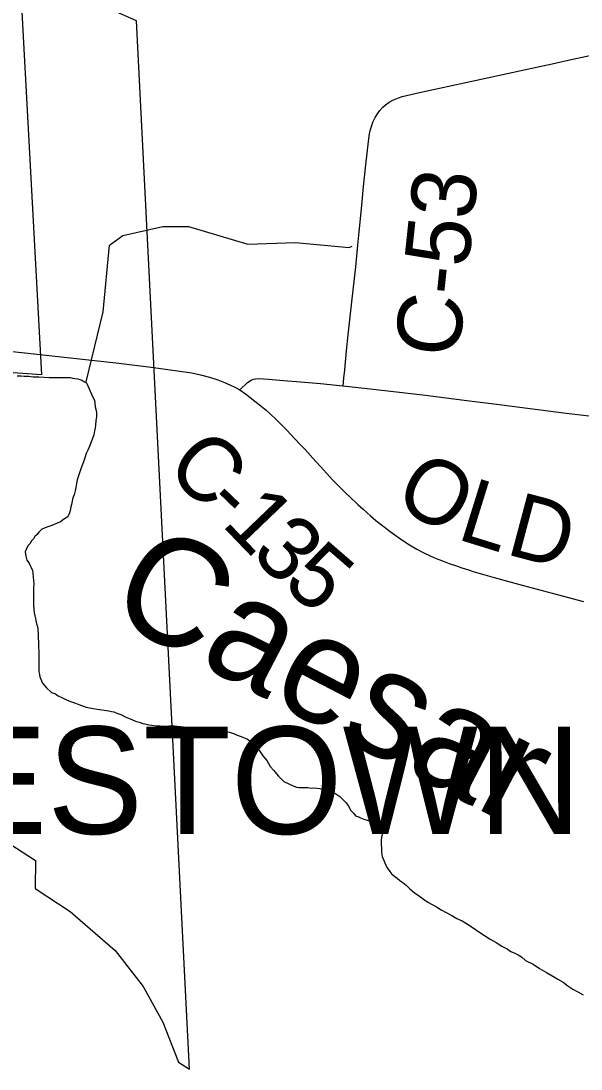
# Model space of a CAD drawing. Extents: x -5.4 to 49.9, y 13.2 to 48.4.
# Drawn here: x 30.099 to 30.593, y 42.966 to 43.891 of the extents above; entities that cross this region are included whole.
import ezdxf

# ---------------------------------------------------------------- set-up
doc = ezdxf.new("R2010")
doc.units = 0
for name, color, linetype in [('GM_X_Corporation', 7, 'Continuous'), ('GM_X_Corporation_Text', 7, 'Continuous'), ('GM_X_County_Road', 7, 'Continuous'), ('GM_X_County_Road_Text', 7, 'Continuous'), ('GM_X_Minor_River', 7, 'Continuous'), ('GM_X_Minor_River_Text', 7, 'Continuous'), ('GM_X_State_Route', 7, 'Continuous')]:
    doc.layers.add(name, color=color, linetype=linetype)

msp = doc.modelspace()

# ---------------------------------------------------------------- linework, layer by layer
at = {"layer": 'GM_X_Corporation'}
for points in [[(30.0978, 43.93683), (30.11717, 43.57845), (30.00085, 43.58666), (30.01955, 43.85142), (30.01808, 43.85261), (30.01694, 43.88966), (29.99211, 43.89093)], [(29.28308, 43.68973), (29.34531, 43.6481), (30.11202, 43.14996), (30.11178, 43.12523), (30.14245, 43.10478), (30.18213, 43.0705), (30.20678, 43.03863), (30.22422, 43.00735), (30.23805, 42.97187), (30.24767, 42.96585), (30.20088, 43.89052), (30.17852, 43.90074)]]:
    msp.add_lwpolyline(points, dxfattribs=at)
at = {"layer": 'GM_X_County_Road'}
for points in [[(30.38315, 43.56867), (30.38383, 43.5753), (30.38459, 43.5827), (30.38617, 43.5994), (30.38769, 43.61361), (30.39088, 43.64264), (30.39438, 43.67348), (30.3961, 43.69266), (30.39726, 43.70441), (30.39932, 43.72481), (30.40126, 43.74459), (30.40332, 43.76371), (30.40549, 43.78411), (30.40656, 43.79093), (30.40731, 43.79472), (30.40846, 43.79846), (30.40944, 43.80126), (30.41136, 43.80527), (30.41334, 43.80854), (30.41562, 43.81161), (30.41821, 43.81441), (30.42055, 43.81655), (30.42365, 43.81883), (30.42643, 43.8204), (30.42912, 43.82164), (30.43186, 43.82271), (30.43522, 43.82378), (30.45042, 43.82733), (30.46803, 43.83121), (30.48989, 43.83595), (30.5494, 43.8488), (30.56758, 43.85286), (30.58154, 43.85594), (30.65259, 43.87134)], [(30.29211, 43.56501), (30.29708, 43.56164), (30.30097, 43.55862), (30.30428, 43.556), (30.30774, 43.5534), (30.31105, 43.55068), (30.31531, 43.54711), (30.31896, 43.54379), (30.32434, 43.53868), (30.32872, 43.53432), (30.33353, 43.52949), (30.33692, 43.52589), (30.34496, 43.51728), (30.34966, 43.51232), (30.3589, 43.50229), (30.36351, 43.49726), (30.37396, 43.48577), (30.3791, 43.48035), (30.38521, 43.47413), (30.38927, 43.47027), (30.39608, 43.46388), (30.40071, 43.45971), (30.40724, 43.45395), (30.41202, 43.44996), (30.4193, 43.4441), (30.42478, 43.43998), (30.43085, 43.43561), (30.43499, 43.43282), (30.44181, 43.42844), (30.44824, 43.42461), (30.45426, 43.42131), (30.45991, 43.41862), (30.46507, 43.41639), (30.47086, 43.4141), (30.4767, 43.41193), (30.48316, 43.40968), (30.48788, 43.40809), (30.49381, 43.40621), (30.49796, 43.40491), (30.50271, 43.40345), (30.50806, 43.4018), (30.51642, 43.39941), (30.53138, 43.3954), (30.54096, 43.39279), (30.56734, 43.38565), (30.59496, 43.37833)]]:
    msp.add_lwpolyline(points, dxfattribs=at)
at = {"layer": 'GM_X_Minor_River'}
for points in [[(30.15659, 43.57208), (30.1716, 43.63393), (30.17719, 43.69269), (30.18909, 43.70121), (30.2241, 43.70931), (30.24683, 43.70927), (30.29923, 43.69351), (30.34132, 43.69502), (30.38861, 43.69074), (30.39128, 43.69183)], [(30.09592, 43.57756), (30.09933, 43.57752), (30.10199, 43.57712), (30.10578, 43.57707), (30.10995, 43.57665), (30.11488, 43.57659), (30.11943, 43.57616), (30.12398, 43.57611), (30.12853, 43.57606), (30.13233, 43.57601), (30.13612, 43.57597), (30.13953, 43.57593), (30.14257, 43.5759), (30.14446, 43.5755), (30.14635, 43.5751), (30.14939, 43.57468), (30.15279, 43.5735), (30.15467, 43.57234), (30.15694, 43.57118), (30.1625, 43.55858), (30.16399, 43.5559), (30.16434, 43.55323), (30.16468, 43.55019), (30.1654, 43.54676), (30.16576, 43.54486), (30.16573, 43.54144), (30.16531, 43.53765), (30.16489, 43.53385), (30.16449, 43.53158), (30.16408, 43.52892), (30.16328, 43.52551), (30.16211, 43.5221), (30.16094, 43.51908), (30.15977, 43.51605), (30.15821, 43.51189), (30.15666, 43.50887), (30.15548, 43.50508), (30.1543, 43.50167), (30.15274, 43.49789), (30.15157, 43.49448), (30.15078, 43.49183), (30.14961, 43.48843), (30.14882, 43.48578), (30.14803, 43.48237), (30.14761, 43.47895), (30.14682, 43.47592), (30.14603, 43.47251), (30.14486, 43.46986), (30.14445, 43.46683), (30.14366, 43.4638), (30.14326, 43.4619), (30.14246, 43.45849), (30.14206, 43.4566), (30.14051, 43.45319), (30.13669, 43.45058), (30.13401, 43.44871), (30.13058, 43.44723), (30.12639, 43.44537), (30.12296, 43.44427), (30.11763, 43.44205), (30.11494, 43.43942), (30.1134, 43.43754), (30.11149, 43.43566), (30.11033, 43.43378), (30.10841, 43.4319), (30.10687, 43.42926), (30.10533, 43.42737), (30.10378, 43.42435), (30.103, 43.42208), (30.10334, 43.41828), (30.10444, 43.41484), (30.10631, 43.41216), (30.10742, 43.41025), (30.10816, 43.40834), (30.10927, 43.40567), (30.10963, 43.40339), (30.10997, 43.39996), (30.11032, 43.39692)], [(30.11032, 43.39692), (30.11066, 43.39388), (30.11025, 43.39046), (30.11021, 43.38704), (30.11018, 43.38438), (30.11015, 43.38096), (30.11012, 43.3783), (30.11008, 43.37489), (30.11043, 43.37146), (30.11077, 43.36842), (30.1115, 43.36575), (30.11186, 43.36347), (30.11222, 43.36156), (30.11295, 43.35851), (30.11368, 43.35623), (30.11403, 43.35356), (30.11437, 43.34976), (30.11434, 43.34672), (30.11467, 43.34216), (30.11462, 43.33798), (30.11497, 43.33456), (30.11488, 43.32582), (30.11485, 43.32316), (30.11482, 43.32088), (30.1148, 43.3186), (30.11478, 43.31632), (30.11551, 43.31403), (30.11586, 43.31175), (30.11808, 43.3064), (30.12183, 43.30218), (30.12596, 43.29796), (30.12974, 43.29677), (30.132, 43.29523), (30.13578, 43.29329), (30.13993, 43.29134), (30.14371, 43.28978), (30.14711, 43.2886), (30.15013, 43.28743), (30.1524, 43.28664), (30.15429, 43.28586), (30.15656, 43.28507), (30.15959, 43.28466), (30.163, 43.28386), (30.16641, 43.28344), (30.17663, 43.28181), (30.17891, 43.2814), (30.18118, 43.281), (30.18382, 43.27983), (30.18723, 43.27865), (30.191, 43.27671), (30.19553, 43.27476), (30.20006, 43.27281), (30.20422, 43.27162), (30.20649, 43.27083), (30.20838, 43.27043), (30.21179, 43.26963), (30.21444, 43.26922), (30.21823, 43.2688), (30.22203, 43.26876), (30.22582, 43.26834), (30.22962, 43.26867), (30.23417, 43.26862), (30.23985, 43.26818), (30.24516, 43.26736), (30.25046, 43.26654), (30.25691, 43.26609), (30.26183, 43.26565), (30.26524, 43.26523), (30.2679, 43.2652), (30.27018, 43.26518), (30.27359, 43.26476), (30.27586, 43.26473), (30.27776, 43.26433), (30.2804, 43.26354), (30.28306, 43.26313), (30.28646, 43.26195), (30.28986, 43.2604), (30.29326, 43.25922), (30.29893, 43.25687), (30.30156, 43.25494), (30.30419, 43.25264), (30.30682, 43.24995), (30.30944, 43.2465), (30.31243, 43.24228), (30.3158, 43.23807), (30.31878, 43.23271), (30.32216, 43.22926), (30.3244, 43.22619), (30.32628, 43.22427), (30.32853, 43.22197), (30.33078, 43.21966), (30.33984, 43.21538), (30.34211, 43.21459), (30.344, 43.21419), (30.3478, 43.21415), (30.3497, 43.21413), (30.35197, 43.2141), (30.35462, 43.21369), (30.3569, 43.21405), (30.35993, 43.21363), (30.36258, 43.21323)], [(30.36258, 43.21323), (30.36561, 43.21243), (30.36902, 43.21163), (30.37205, 43.21084), (30.37393, 43.21006), (30.37582, 43.20928), (30.37846, 43.20735), (30.38034, 43.20619), (30.38222, 43.20426), (30.3841, 43.20234), (30.38598, 43.2008), (30.38784, 43.19774), (30.39008, 43.19392), (30.39271, 43.19123), (30.39421, 43.18931), (30.39609, 43.18853), (30.39836, 43.18737), (30.40138, 43.18619), (30.40441, 43.1854), (30.40706, 43.18461), (30.40933, 43.1842), (30.41196, 43.18265), (30.41346, 43.18074), (30.41534, 43.17881), (30.41645, 43.17614), (30.41756, 43.17309), (30.41715, 43.17044), (30.41674, 43.16778), (30.41671, 43.16436), (30.41704, 43.16056), (30.417, 43.15676), (30.41773, 43.15333), (30.4218, 43.14379), (30.42367, 43.14111), (30.42591, 43.13804), (30.42855, 43.13611), (30.4308, 43.13419), (30.43306, 43.13226), (30.4357, 43.13033), (30.43871, 43.12802), (30.44209, 43.12494), (30.44585, 43.12148), (30.45037, 43.11839), (30.45413, 43.11569), (30.4579, 43.11298), (30.46167, 43.11104), (30.46544, 43.1091), (30.46959, 43.10639), (30.47412, 43.10406), (30.47902, 43.10135), (30.48355, 43.09864), (30.48808, 43.09669), (30.49185, 43.09436), (30.49788, 43.0905), (30.50278, 43.08702), (30.50767, 43.08355), (30.51295, 43.08045), (30.51823, 43.07735), (30.52313, 43.07426), (30.52766, 43.07192), (30.53105, 43.06961), (30.53444, 43.06805), (30.53746, 43.0665), (30.54048, 43.06494), (30.54386, 43.06148), (30.55066, 43.05837), (30.55631, 43.0545), (30.56234, 43.05102), (30.568, 43.04791), (30.57252, 43.0452), (30.57705, 43.04249), (30.58119, 43.0394), (30.58571, 43.03631), (30.59024, 43.03398), (30.59476, 43.03127)]]:
    msp.add_lwpolyline(points, dxfattribs=at)
at = {"layer": 'GM_X_State_Route'}
for points in [[(30.0288, 43.60393), (30.0298, 43.60387), (30.0307, 43.60382), (30.06198, 43.60198), (30.0891, 43.59908), (30.15088, 43.59232), (30.18547, 43.58851), (30.21386, 43.58513), (30.23726, 43.58194), (30.24978, 43.58024), (30.25757, 43.57846), (30.26537, 43.57634), (30.27263, 43.57386), (30.27847, 43.57156), (30.28343, 43.56943), (30.28822, 43.56713), (30.29211, 43.56501)], [(30.29211, 43.56501), (30.29894, 43.57161), (30.30225, 43.57357), (30.30407, 43.57439), (30.30601, 43.57489), (30.30865, 43.57505), (30.31743, 43.57455), (30.33412, 43.57311), (30.34215, 43.5724), (30.36318, 43.57063), (30.38296, 43.56869), (30.38315, 43.56867), (30.40703, 43.56601), (30.45334, 43.56071), (30.49218, 43.55576), (30.52299, 43.55176), (30.57971, 43.54464), (30.60006, 43.54221)]]:
    msp.add_lwpolyline(points, dxfattribs=at)

# ---------------------------------------------------------------- texts
at = {"layer": 'GM_X_Corporation_Text'}
msp.add_text('JAMESTOWN', height=0.094697, rotation=0.00001, dxfattribs=at).set_placement((29.78462, 43.1733))
at = {"layer": 'GM_X_County_Road_Text'}
for s, height, rotation, p in [('C-53', 0.056818, 83.92038, (30.48495, 43.59254)), ('C', 0.05682, 316.66716, (30.22491, 43.49407)), ('O', 0.05682, 328.99939, (30.4258, 43.46563)), ('L', 0.05682, 342.74121, (30.48221, 43.43381)), ('-', 0.05682, 316.06531, (30.25874, 43.46216)), ('1', 0.05682, 313.82246, (30.27513, 43.44638)), ('D', 0.05682, 345.15027, (30.5253, 43.42048)), ('3', 0.05682, 315.49297, (30.30064, 43.41984)), ('5', 0.05682, 319.05525, (30.32843, 43.39269))]:
    msp.add_text(s, height=height, rotation=rotation, dxfattribs=at).set_placement(p)
at = {"layer": 'GM_X_Minor_River_Text'}
msp.add_text('Caesar', height=0.094689, rotation=332.49488, dxfattribs=at).set_placement((30.17267, 43.36663))

doc.saveas('drawing.dxf')
